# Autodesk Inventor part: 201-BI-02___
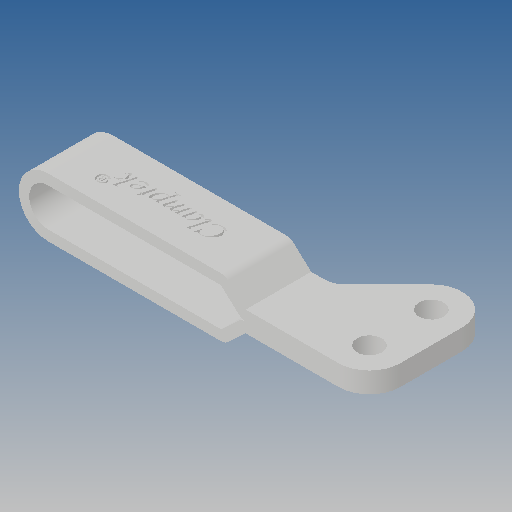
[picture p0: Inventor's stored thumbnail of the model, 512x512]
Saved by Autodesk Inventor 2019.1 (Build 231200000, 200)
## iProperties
Created: 2010-06
Part Number: 201-BI-02___
Material: Ogólny
Document SubType Name: Modeling
Designer: CADENGINEERING4
Density: 1 g/cm^3
Appearance: Domyślna
Author: CADENGINEERING4
Revision Number: ANY
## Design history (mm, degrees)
feature "NONE"
node "Bryła1"
